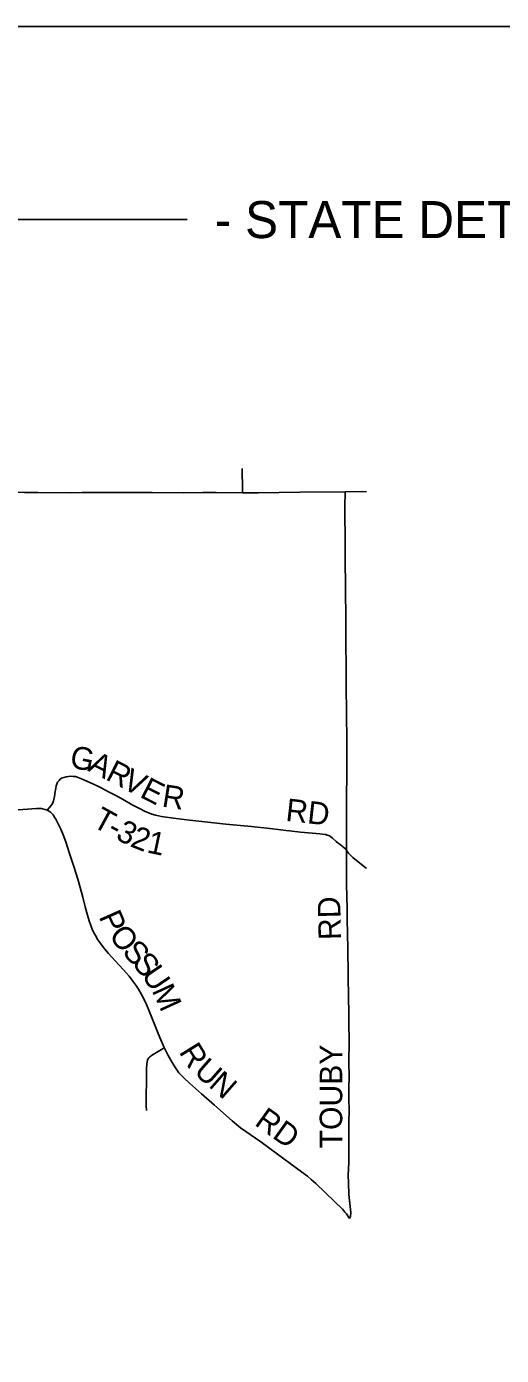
# Model space of a CAD drawing. Extents: x 40529 to 41139, y 15164 to 15584.
# Drawn here: x 40711.9 to 40747.9, y 15483.8 to 15584.3 of the extents above; entities that cross this region are included whole.
import ezdxf

# ---------------------------------------------------------------- set-up
doc = ezdxf.new("R2010")
doc.units = 0
for name, color, linetype in [('GM_X_County_Road', 7, 'Continuous'), ('GM_X_County_Road_Text', 7, 'Continuous'), ('GM_X_Township_Road', 7, 'Continuous'), ('GM_X_Township_Road_Text', 7, 'Continuous'), ('SC_Scratch1', 7, 'Continuous'), ('SH_Data', 7, 'Continuous'), ('SH_Text', 7, 'Continuous')]:
    doc.layers.add(name, color=color, linetype=linetype)

msp = doc.modelspace()

# ---------------------------------------------------------------- linework, layer by layer
at = {"layer": 'GM_X_County_Road'}
for p, q in [((40712.77, 15549.06), (40715.24, 15549.05)), ((40736.04, 15549.12), (40737.65, 15549.13))]:
    msp.add_line(p, q, dxfattribs=at)
for points in [[(40706.42, 15550.66), (40707.39, 15550.32), (40708.75, 15549.81), (40708.96, 15549.72), (40709.41, 15549.56), (40709.57, 15549.5), (40710.02, 15549.36), (40710.29, 15549.28), (40710.56, 15549.22), (40710.93, 15549.15), (40711.3, 15549.1), (40711.77, 15549.07), (40712.23, 15549.06), (40712.77, 15549.06)], [(40715.24, 15549.05), (40716.13, 15549.06), (40717.53, 15549.07), (40719.95, 15549.06), (40720.33, 15549.06)], [(40720.33, 15549.06), (40721.44, 15549.07), (40723.77, 15549.05), (40725.26, 15549.06), (40726.28, 15549.06), (40728.26, 15549.05)], [(40728.26, 15549.05), (40729.45, 15549.05), (40732.62, 15549.08), (40736.04, 15549.12)], [(40705.52, 15524.41), (40705.89, 15524.45), (40705.98, 15524.47), (40706.07, 15524.48), (40706.16, 15524.5), (40706.32, 15524.54), (40707, 15524.71), (40707.46, 15524.81), (40707.73, 15524.86), (40708.11, 15524.91), (40708.5, 15524.94), (40708.57, 15524.94), (40711.64, 15525.09), (40712.67, 15525.15), (40712.86, 15525.16), (40713.05, 15525.15), (40713.14, 15525.14), (40713.33, 15525.09), (40713.42, 15525.06), (40713.49, 15525.03)], [(40713.49, 15525.03), (40713.59, 15524.98), (40713.67, 15524.93), (40713.74, 15524.87), (40713.81, 15524.81), (40713.94, 15524.67), (40714.05, 15524.51), (40714.14, 15524.35), (40714.27, 15524.1), (40714.51, 15523.59), (40714.69, 15523.16), (40714.89, 15522.64), (40715.16, 15521.84), (40715.51, 15520.78), (40715.81, 15519.8), (40715.99, 15519.17), (40716.18, 15518.45), (40716.37, 15517.73), (40716.53, 15517.09), (40716.66, 15516.65), (40716.78, 15516.3), (40716.89, 15516.04), (40717, 15515.79), (40717.14, 15515.55), (40717.33, 15515.23), (40717.54, 15514.92), (40717.83, 15514.55), (40718.13, 15514.19), (40718.63, 15513.64), (40719.25, 15512.95), (40719.68, 15512.46), (40719.98, 15512.09), (40720.2, 15511.79), (40720.4, 15511.48), (40720.63, 15511.09), (40720.81, 15510.77), (40721.01, 15510.34), (40721.19, 15509.91), (40721.83, 15508.26), (40722.01, 15507.83), (40722.35, 15507.07)], [(40722.35, 15507.07), (40722.65, 15506.48), (40722.95, 15505.93), (40723.14, 15505.61), (40723.29, 15505.38), (40723.46, 15505.16), (40723.65, 15504.95), (40723.84, 15504.75), (40724.25, 15504.37), (40725.16, 15503.57), (40726.14, 15502.71), (40727.47, 15501.54), (40727.82, 15501.24), (40728.11, 15501.01), (40729.64, 15499.93), (40730.92, 15499), (40732.73, 15497.68), (40733.17, 15497.34), (40733.46, 15497.1), (40733.81, 15496.79), (40735.22, 15495.43), (40735.82, 15494.84), (40736.01, 15494.63), (40736.13, 15494.49), (40736.37, 15494.14)]]:
    msp.add_lwpolyline(points, dxfattribs=at)
at = {"layer": 'GM_X_Township_Road'}
for points in [[(40728.26, 15549.05), (40728.26, 15549.24), (40728.24, 15550.88)], [(40736.13, 15521.98), (40736.13, 15522.04), (40736.14, 15522.4), (40736.12, 15525.26), (40736.16, 15528.52), (40736.15, 15530.48), (40736.13, 15532.15), (40736.11, 15534.66), (40736.11, 15535.41), (40736.1, 15536.25), (40736.09, 15537.27), (40736.08, 15538.76), (40736.07, 15540.21), (40736.06, 15541.01), (40736.06, 15542.2), (40736.04, 15543.69), (40736.02, 15544.65), (40736.02, 15546.03), (40736.01, 15546.97), (40736.01, 15548.27), (40736.02, 15548.83), (40736.03, 15548.92), (40736.04, 15549.12)], [(40713.49, 15525.03), (40713.65, 15525.2), (40713.8, 15525.38), (40713.85, 15525.46), (40713.91, 15525.59), (40713.94, 15525.66), (40713.96, 15525.74), (40713.99, 15525.85), (40714.03, 15526.06), (40714.1, 15526.44), (40714.14, 15526.67), (40714.18, 15526.88), (40714.22, 15526.99), (40714.28, 15527.14), (40714.39, 15527.28), (40714.47, 15527.37), (40714.58, 15527.45), (40714.75, 15527.51), (40714.92, 15527.55), (40715.1, 15527.58), (40715.28, 15527.61), (40715.46, 15527.59), (40715.64, 15527.57), (40715.84, 15527.51), (40716.08, 15527.41), (40716.26, 15527.33), (40716.77, 15527.1), (40716.95, 15527.02), (40717.37, 15526.82), (40717.62, 15526.69), (40717.7, 15526.64), (40718.28, 15526.35), (40718.69, 15526.14), (40719.18, 15525.87), (40719.98, 15525.41), (40720.48, 15525.15), (40720.9, 15524.94), (40721.24, 15524.8), (40721.41, 15524.73), (40721.68, 15524.66), (40722.13, 15524.56), (40722.31, 15524.53), (40723.04, 15524.43), (40724.05, 15524.3), (40727, 15523.98), (40728.95, 15523.79), (40730.33, 15523.64), (40731.17, 15523.55), (40731.53, 15523.5), (40731.81, 15523.46), (40732.64, 15523.37), (40733.56, 15523.28), (40734.12, 15523.23), (40734.49, 15523.2), (40734.58, 15523.18), (40734.67, 15523.15), (40734.76, 15523.12), (40734.85, 15523.08), (40734.93, 15523.03), (40735.08, 15522.91), (40735.36, 15522.66), (40735.49, 15522.54), (40735.64, 15522.43), (40736.07, 15522.07), (40736.13, 15521.98)], [(40736.37, 15494.14), (40736.44, 15494.29), (40736.45, 15494.58), (40736.32, 15495.95), (40736.28, 15496.84), (40736.27, 15497.38), (40736.32, 15498.38), (40736.32, 15498.66), (40736.31, 15499.22), (40736.31, 15499.96), (40736.32, 15501.36), (40736.33, 15502.38), (40736.32, 15503.13), (40736.32, 15503.97), (40736.33, 15504.9), (40736.32, 15505.92), (40736.33, 15507.6), (40736.32, 15508.9), (40736.31, 15509.83), (40736.29, 15510.75), (40736.27, 15512.61), (40736.24, 15514.57), (40736.19, 15516.78), (40736.18, 15517.52), (40736.16, 15518.54), (40736.13, 15519.38), (40736.13, 15520.52), (40736.12, 15520.87), (40736.13, 15521.98)], [(40736.13, 15521.98), (40736.23, 15521.85), (40736.29, 15521.78), (40736.42, 15521.65), (40736.62, 15521.46), (40737.65, 15520.63)], [(40720.99, 15502.31), (40720.98, 15502.65), (40720.97, 15503.01), (40720.98, 15503.38), (40721, 15504.58), (40721, 15504.9), (40721.01, 15505.13), (40721.01, 15505.48), (40721.03, 15505.81), (40721.05, 15505.99), (40721.07, 15506.11), (40721.11, 15506.2), (40721.18, 15506.29), (40721.25, 15506.36), (40721.32, 15506.43), (40721.39, 15506.48), (40721.63, 15506.62), (40722.26, 15507.01), (40722.35, 15507.07)]]:
    msp.add_lwpolyline(points, dxfattribs=at)
at = {"layer": 'SC_Scratch1'}
msp.add_lwpolyline([(40528.65, 15584.31), (41138.65, 15584.31), (41138.65, 15164.31), (40528.65, 15164.31)], close=True, dxfattribs=at)
at = {"layer": 'SH_Data'}
msp.add_line((40707.68, 15569.71), (40724.09, 15569.71), dxfattribs=at)

# ---------------------------------------------------------------- texts
at = {"layer": 'GM_X_County_Road_Text'}
for s, height, rotation, p in [('P', 1.71, 293.8761, (40717.37, 15516.98)), ('O', 1.71, 308.8223, (40718.09, 15515.51)), ('S', 1.71, 312.2816, (40719.1, 15514.26)), ('S', 1.71, 309.37, (40719.86, 15513.42)), ('U', 1.71, 304.1558, (40720.57, 15512.56)), ('M', 1.71, 294.5899, (40721.38, 15511.39)), ('R', 1.71, 301.9123, (40723.42, 15506.74)), ('U', 1.71, 318.6861, (40724.51, 15505.14)), ('N', 1.71, 318.8883, (40725.64, 15504.15)), ('RD', 1.706, 324.4048, (40729.1, 15501.26))]:
    msp.add_text(s, height=height, rotation=rotation, dxfattribs=at).set_placement(p)
at = {"layer": 'GM_X_Township_Road_Text'}
for s, height, rotation, p in [('G', 1.71, 349.4824, (40715.13, 15528.27)), ('A', 1.71, 333.7608, (40716.49, 15528.04)), ('R', 1.71, 333.1068, (40717.83, 15527.38)), ('V', 1.71, 333.101, (40719.08, 15526.74)), ('E', 1.71, 333.1438, (40720.42, 15526.06)), ('R', 1.71, 351.0237, (40722.11, 15525.31)), ('RD', 1.706, 353.5985, (40731.48, 15524.23)), ('T', 1.71, 331.3263, (40716.82, 15523.85)), ('-', 1.71, 331.582, (40717.94, 15523.23)), ('3', 1.71, 332.7286, (40718.59, 15522.88)), ('2', 1.71, 338.1799, (40719.69, 15522.32)), ('1', 1.71, 348.1154, (40720.97, 15521.84)), ('RD', 1.706, 91.4624, (40735.73, 15515.23)), ('TOUBY', 1.706, 90, (40735.81, 15499.44))]:
    msp.add_text(s, height=height, rotation=rotation, dxfattribs=at).set_placement(p)
at = {"layer": 'SH_Text'}
msp.add_text('  - STATE DETOUR', height=2.8, dxfattribs=at).set_placement((40724.09, 15568.31))

doc.saveas('drawing.dxf')
